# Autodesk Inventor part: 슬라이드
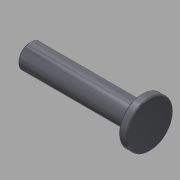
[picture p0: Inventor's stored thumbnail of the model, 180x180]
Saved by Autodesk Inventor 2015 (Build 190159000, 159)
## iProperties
Created: 2015-10
Part Number: 슬라이드
Document SubType Name: Modeling
Designer: mdu
Density: 1 g/cm^3
Material: 강철, 연강
Appearance: 강철 - 광택
Author: mdu
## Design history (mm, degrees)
sketch "스케치1"
  geometry: L1 (-75, 162)-(-75, 58) reference; L2 (-148, 110)-(2, 110); L3 (-148, 110)-(-148, 125); L4 (-148, 125)-(-8, 125); L5 (-8, 125)-(-8, 139); L6 (-8, 139)-(2, 139); L7 (2, 139)-(2, 110); 2 further points
  constraints: 12 end point, 3 parallel, 3 perpendicular, 1 midpoint, 1 point on line
  dimensions: "d0" = 58 diameter of L6 L2; "d1" = 30 diameter of L4 L2; "d2" = 10 distance of L5.end L6.end; "d3" = 150 distance of L2.start L2.end; "d4" = 73 distance between parallel lines of L3 L1
revolve "회전1" sketch "스케치1" stored, may be unused: angle "d5" = 90 deg
hole "구멍1" diameter "d11" = 13.376; stored, may be unused: countersink angle "d15" = 90 deg, drill point angle "d17" = 118 deg; dims "d9" = 10, "d10" = 10, "d12" = 22, "d13" = 4, "d14" = 2, "d16" = 25
chamfer "모따기1" distance "d6" = 1; stored, may be unused: second distance "d7" = 2, angle "d8" = 45 deg
node "솔리드1"
node "참조1"
